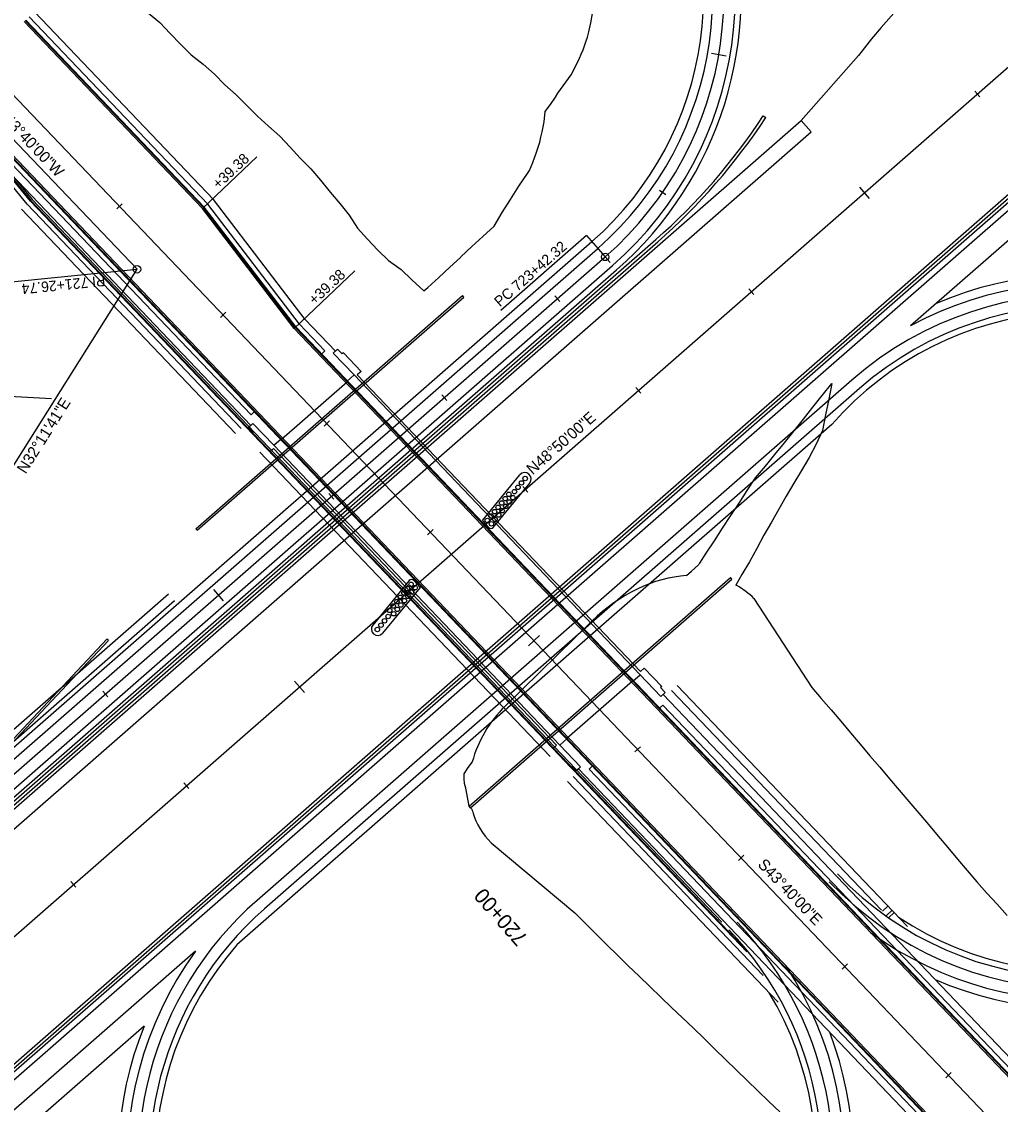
# Model space of a CAD drawing. Extents: x 1300404 to 1323571, y 237813 to 252077.
# Drawn here: x 1310501 to 1311153, y 240634 to 241355 of the extents above; entities that cross this region are included whole.
import ezdxf

# ---------------------------------------------------------------- set-up
doc = ezdxf.new("R2010")
doc.units = 0
for name, color, linetype in [('R_Attenuator', 7, 'Continuous'), ('R_Barrier Wall', 7, 'Continuous'), ('R_Bridge', 7, 'Continuous'), ('R_Bridge Wall', 7, 'Continuous'), ('R_Const Limits', 7, 'Continuous'), ('R_Curb', 7, 'Continuous'), ('R_Future', 7, 'Continuous'), ('R_Horz Alg Annot', 7, 'Continuous'), ('R_Horz Alg Annot Leader', 7, 'Continuous'), ('R_Horz Alg Major Ticks', 7, 'Continuous'), ('R_Horz Alg Minor Ticks', 7, 'Continuous'), ('R_Horz Alg Station Annot', 7, 'Continuous'), ('R_Horz Alg Tangents', 7, 'Continuous'), ('R_Horz Alg Tangents Text', 7, 'Continuous'), ('R_Lane Edge', 7, 'Continuous'), ('R_Proposed', 7, 'Continuous'), ('R_Shoulder', 7, 'Continuous'), ('R_Sidewalk Edge', 7, 'Continuous')]:
    doc.layers.add(name, color=color, linetype=linetype)

msp = doc.modelspace()

# ---------------------------------------------------------------- linework, layer by layer
at = {"layer": 'R_Attenuator'}
for p, q in [((1310807.94, 241022.48), (1310832.88, 241052.88)), ((1310815.12, 241017.82), (1310839.41, 241047.43)), ((1310812.06, 241017.77), (1310807.94, 241022.48)), ((1310759.18, 240982.48), (1310734.86, 240952.84)), ((1310762.21, 240982.5), (1310766.33, 240977.79)), ((1310766.33, 240977.79), (1310741.39, 240947.4))]:
    msp.add_line(p, q, dxfattribs=at)
for centre in [(1310831.59, 241044.6), (1310833.97, 241047.5), (1310836.35, 241050.4), (1310825.48, 241039.91), (1310828.19, 241037.69), (1310829.21, 241041.7), (1310818.34, 241031.21), (1310820.72, 241034.11), (1310823.1, 241037.01), (1310823.43, 241031.89), (1310825.81, 241034.79), (1310813.59, 241025.42), (1310815.97, 241028.31), (1310816.29, 241023.2), (1310818.67, 241026.09), (1310821.05, 241028.99), (1310811.21, 241022.52), (1310813.91, 241020.3), (1310760.36, 240979.97), (1310755.6, 240974.18), (1310757.98, 240977.08), (1310760.68, 240974.86), (1310763.06, 240977.75), (1310748.46, 240965.48), (1310750.84, 240968.38), (1310753.22, 240971.28), (1310753.55, 240966.16), (1310755.93, 240969.06), (1310758.3, 240971.96), (1310745.06, 240958.57), (1310746.08, 240962.58), (1310748.79, 240960.36), (1310751.17, 240963.26), (1310740.3, 240952.77), (1310742.68, 240955.67), (1310737.92, 240949.87)]:
    msp.add_circle(centre, 1.5, dxfattribs=at)
for centre, radius, start, end in [((1310836.13, 241050.13), 4.25, 320.63015, 139.81639), ((1310813.57, 241019.09), 2, 221.17359, 320.63075), ((1310760.7, 240981.18), 2, 41.17359, 140.63075), ((1310738.14, 240950.14), 4.25, 140.63015, 319.81639)]:
    msp.add_arc(centre, radius, start, end, dxfattribs=at)
at = {"layer": 'R_Barrier Wall'}
for p, q in [((1310994.97, 241291.94), (1310996.64, 241290.84)), ((1309593.62, 240046.84), (1310923.44, 241209.65)), ((1309594.94, 240045.34), (1310924.76, 241208.15)), ((1310489.06, 240870.1), (1310557.69, 240943.38)), ((1310490.03, 240869.19), (1310558.66, 240942.47)), ((1310558.66, 240942.47), (1310557.69, 240943.38))]:
    msp.add_line(p, q, dxfattribs=at)
for radius in [404.98, 406.98]:
    msp.add_arc((1310656.34, 241514.05), radius, 311.26571, 326.73874, dxfattribs=at)
at = {"layer": 'R_Bridge'}
for p, q in [((1310708.55, 241133.88), (1310711.44, 241136.64)), ((1310722.36, 241119.42), (1310708.55, 241133.88)), ((1310714.54, 241133.4), (1310711.44, 241136.64)), ((1310715.26, 241134.09), (1310714.54, 241133.4)), ((1310727.01, 241121.78), (1310715.26, 241134.09)), ((1310717.46, 241115.13), (1310722.36, 241119.42)), ((1310727, 241121.8), (1310724.52, 241119.44)), ((1310724.52, 241119.44), (1310913.14, 240921.84)), ((1310674.09, 241076.57), (1310717.79, 241114.79)), ((1310717.79, 241114.79), (1310717.46, 241115.13)), ((1310655.03, 241087.12), (1310652.14, 241084.35)), ((1310655.25, 241081.1), (1310652.14, 241084.35)), ((1310668.84, 241072.65), (1310655.03, 241087.12)), ((1310655.25, 241081.1), (1310654.52, 241080.41)), ((1310666.26, 241068.11), (1310654.52, 241080.41)), ((1310668.87, 241072.67), (1310673.74, 241076.93)), ((1310674.09, 241076.57), (1310673.74, 241076.93)), ((1310668.73, 241070.47), (1310666.26, 241068.11)), ((1310668.73, 241070.47), (1310857.35, 240872.87)), ((1310668.87, 241072.67), (1310668.84, 241072.65)), ((1310915.61, 240924.2), (1310913.14, 240921.84)), ((1310915.59, 240924.21), (1310927.35, 240911.9)), ((1310908.12, 240915.39), (1310912.99, 240919.65)), ((1310912.99, 240919.65), (1310913.01, 240919.67)), ((1310913.01, 240919.67), (1310926.82, 240905.21)), ((1310864.08, 240877.52), (1310907.78, 240915.74)), ((1310907.78, 240915.74), (1310908.12, 240915.39)), ((1310927.35, 240911.9), (1310926.62, 240911.21)), ((1310926.62, 240911.21), (1310929.71, 240907.97)), ((1310926.82, 240905.21), (1310929.71, 240907.97)), ((1310854.87, 240870.51), (1310857.35, 240872.87)), ((1310859.51, 240872.89), (1310864.41, 240877.18)), ((1310859.51, 240872.89), (1310873.32, 240858.43)), ((1310864.08, 240877.52), (1310864.41, 240877.18)), ((1310854.86, 240870.53), (1310866.61, 240858.21)), ((1310866.61, 240858.21), (1310867.34, 240858.9)), ((1310867.34, 240858.9), (1310870.43, 240855.66)), ((1310873.32, 240858.43), (1310870.43, 240855.66))]:
    msp.add_line(p, q, dxfattribs=at)
at = {"layer": 'R_Bridge Wall'}
for p, q in [((1310617, 241016.96), (1310794.66, 241172.31)), ((1310617.87, 241015.96), (1310795.53, 241171.31)), ((1310795.53, 241171.31), (1310794.66, 241172.31)), ((1310617.87, 241015.96), (1310617, 241016.96)), ((1310799.12, 240832.17), (1310973.27, 240984.44)), ((1310800, 240831.16), (1310974.14, 240983.43)), ((1310974.14, 240983.43), (1310973.27, 240984.44)), ((1310800, 240831.16), (1310799.12, 240832.17))]:
    msp.add_line(p, q, dxfattribs=at)
at = {"layer": 'R_Const Limits'}
for p, q in [((1310988.78, 240970.54), (1311027.32, 240911.3)), ((1310823.12, 240898.9), (1310880.92, 240955.54)), ((1310799.12, 240832.17), (1310800.89, 240830.14)), ((1310813.77, 240807.78), (1310869.51, 240761.06))]:
    msp.add_line(p, q, dxfattribs=at)
for points in [[(1311185.37, 241483.83), (1311167.13, 241464.86), (1311167.15, 241464.85), (1311162.87, 241459.25), (1311156.66, 241451.34), (1311153.67, 241440.35), (1311146.91, 241432.97), (1311139.94, 241425.8), (1311132.94, 241418.66), (1311125.71, 241411.74), (1311119.16, 241404.16), (1311112.06, 241397.12), (1311106.62, 241388.47), (1311100.11, 241380.86), (1311093.57, 241373.27), (1311086.77, 241365.95), (1311080.19, 241358.4), (1311073.62, 241350.85), (1311067.08, 241343.26), (1311060.89, 241335.34), (1311058.51, 241332.25), (1311020.24, 241288.97), (1311020.24, 241288.97)], [(1310585.25, 241360.65), (1310592.98, 241354.21), (1310599.76, 241346.86), (1310606.77, 241339.72), (1310613.83, 241332.64), (1310621.86, 241326.48), (1310629.31, 241319.77), (1310636.38, 241312.69), (1310643.86, 241306), (1310650.82, 241298.83), (1310657.93, 241291.79), (1310665.37, 241285.06), (1310672.88, 241278.41), (1310679.73, 241271.12), (1310686.52, 241263.78), (1310693.62, 241256.74), (1310700.09, 241249.08), (1310706.37, 241241.25), (1310712.81, 241233.58), (1310719.08, 241225.74), (1310724.68, 241217.25), (1310731.35, 241209.8), (1310738.15, 241202.47), (1310745.41, 241195.57), (1310753.67, 241189.63), (1310760.91, 241182.72), (1310768.85, 241175.36)], [(1310839.27, 241255.69), (1310839.27, 241255.69), (1310841.49, 241260.84), (1310843.87, 241267.73), (1310846.06, 241274.43), (1310846.91, 241277.88), (1310847.7, 241281.28), (1310849.05, 241288), (1310849.61, 241294.95), (1310853.25, 241299.62), (1310856.55, 241304.55), (1310858.13, 241307.06), (1310859.91, 241309.48), (1310863.56, 241314.35), (1310867.11, 241319.38), (1310869.81, 241324.85), (1310872.55, 241330.36), (1310873.77, 241333.2), (1310874.93, 241336.06), (1310877.05, 241341.89), (1310877.89, 241344.5), (1310878.8, 241347.86), (1310880.17, 241353.93), (1310881.19, 241360.09)], [(1310768.85, 241175.37), (1310771.5, 241177.75), (1310778.93, 241184.44), (1310786.26, 241191.26), (1310793.21, 241197.72), (1310793.58, 241198.08), (1310800.87, 241204.93), (1310808.19, 241211.75), (1310815.61, 241218.45), (1310820.95, 241227.54), (1310826.51, 241236.38), (1310832.2, 241245.06), (1310837.94, 241253.69), (1310839.27, 241255.69), (1310839.27, 241255.69)], [(1310943.96, 240985.79), (1310947.24, 240988.69), (1310951.89, 240992.93), (1310952.15, 240993.31), (1310952.55, 240993.92), (1310952.65, 240994.08), (1310956.95, 241000.61), (1310962.45, 241008.98), (1310967.82, 241017.42), (1310973.35, 241025.76), (1310978.89, 241034.1), (1310984.27, 241042.54), (1310989.93, 241050.81), (1310996.41, 241058.59), (1311002.8, 241066.42), (1311009.11, 241074.29), (1311015.49, 241082.13), (1311021.8, 241090.01), (1311028.05, 241097.93), (1311034.31, 241105.84), (1311040.66, 241113.69), (1311038.66, 241103.24), (1311036.53, 241092.87), (1311034.46, 241082.46), (1311030.27, 241073.32), (1311025.53, 241064.5), (1311020.53, 241055.84), (1311015.36, 241047.28), (1311010.37, 241038.61), (1311005.4, 241029.93), (1311000.43, 241021.25), (1310995.33, 241012.65), (1310990.62, 241003.82), (1310985.89, 240995), (1310980.66, 240986.47), (1310976.81, 240979.35)], [(1311027.33, 240911.29), (1311033.68, 240903.93), (1311040.19, 240896.32), (1311046.68, 240888.7), (1311053.17, 240881.07), (1311059.64, 240873.42), (1311066.1, 240865.76), (1311072.56, 240858.1), (1311079.08, 240850.5), (1311085.58, 240842.88), (1311092.07, 240835.25), (1311098.55, 240827.61), (1311105.01, 240819.96), (1311111.46, 240812.29), (1311117.9, 240804.61), (1311124.32, 240796.91), (1311130.76, 240789.24), (1311137.39, 240781.74), (1311144.05, 240774.27), (1311150.76, 240766.85), (1311157.47, 240759.43)], [(1310799.12, 240832.17), (1310796.95, 240844.17), (1310795.93, 240847.21), (1310795.63, 240850.43), (1310795.75, 240853.8), (1310798.3, 240857.98), (1310801.17, 240861.66)], [(1311005.93, 240628.61), (1310998.7, 240635.54), (1310991.49, 240642.48), (1310984.28, 240649.42), (1310977.09, 240656.38), (1310969.93, 240663.37), (1310962.78, 240670.37), (1310955.65, 240677.39), (1310948.44, 240684.33), (1310941.18, 240691.23), (1310933.93, 240698.14), (1310926.7, 240705.05), (1310919.48, 240711.99), (1310912.27, 240718.93), (1310905.07, 240725.89), (1310897.89, 240732.85), (1310890.72, 240739.83), (1310883.57, 240746.83), (1310876.53, 240753.94), (1310869.51, 240761.06), (1310869.51, 240761.06), (1310869.51, 240761.06), (1310869.51, 240761.06), (1310869.51, 240761.06), (1310869.51, 240761.06), (1310869.51, 240761.06), (1310869.51, 240761.06), (1310869.51, 240761.06)]]:
    msp.add_lwpolyline(points, dxfattribs=at)
for centre, major_axis, ratio, start_param, end_param in [((1310926.5, 240908.22), (-62.28, -62.32), 0.745616, 3.84485, 4.698226), ((1310926.5, 240908.22), (-62.28, -62.32), 0.745616, 3.358393, 3.367118), ((1310926.5, 240908.22), (-62.28, -62.32), 0.745616, 3.141593, 3.358393), ((1310862.67, 240857.7), (48.9, 49.92), 0.817242, 1.545592, 2.183789), ((1310862.67, 240857.7), (48.9, 49.92), 0.817242, 2.691395, 2.723332), ((1310862.67, 240857.7), (48.9, 49.92), 0.817242, 2.723644, 3.141593)]:
    msp.add_ellipse(centre, major_axis=major_axis, ratio=ratio, start_param=start_param, end_param=end_param, dxfattribs=at)
at = {"layer": 'R_Curb'}
for p, q in [((1310503.29, 241355.44), (1310622.23, 241230.84)), ((1310503.65, 241355.78), (1310622.61, 241231.16)), ((1310431.61, 241329.88), (1310671.61, 241078.44)), ((1310431.97, 241330.23), (1310671.99, 241078.77)), ((1310683.32, 241150.91), (1310622.23, 241230.84)), ((1310683.7, 241151.23), (1310622.61, 241231.16)), ((1310683.32, 241150.91), (1311065.94, 240750.04)), ((1310683.7, 241151.23), (1311067.92, 240748.69)), ((1310671.61, 241078.44), (1311009.39, 240724.57)), ((1310671.99, 241078.77), (1311008.13, 240726.61)), ((1311065.94, 240750.04), (1311239.97, 240567.73)), ((1311067.92, 240748.69), (1311240.13, 240568.28)), ((1311008.13, 240726.61), (1311199.03, 240526.61)), ((1311009.39, 240724.57), (1311198.47, 240526.48))]:
    msp.add_line(p, q, dxfattribs=at)
at = {"layer": 'R_Future'}
for p, q in [((1311714.76, 241726.24), (1309950.43, 240183.5)), ((1311716.07, 241724.73), (1309951.75, 240181.99)), ((1311717.39, 241723.23), (1309953.06, 240180.49)), ((1311720.02, 241720.22), (1309955.69, 240177.48)), ((1311729.9, 241708.92), (1311093.16, 241152.15)), ((1310504.53, 241233.21), (1310408.91, 241349.31)), ((1310506.77, 241235.21), (1310411.16, 241351.31)), ((1310411.52, 241351.65), (1310507.13, 241235.55)), ((1310412.25, 241352.34), (1310507.86, 241236.24)), ((1310506.77, 241235.21), (1310984.1, 240735.13)), ((1310506.77, 241235.21), (1310984.1, 240735.13)), ((1310507.13, 241235.55), (1310981.19, 240738.9)), ((1310507.13, 241235.55), (1310981.19, 240738.9)), ((1310507.86, 241236.24), (1310967.32, 240754.88)), ((1310507.86, 241236.24), (1310967.32, 240754.88)), ((1310500.78, 241229.89), (1310643.48, 241080.39)), ((1310504.53, 241233.21), (1310647.25, 241083.69)), ((1311054.08, 241115.99), (1310657.74, 240769.43)), ((1310426.48, 241108.99), (1310520.85, 241103.66)), ((1311059.02, 241110.35), (1310662.67, 240763.78)), ((1311040.69, 241086.35), (1310644.34, 240739.78)), ((1310659.55, 241067.9), (1310853.07, 240865.17)), ((1309569.9, 240073.92), (1310598.82, 240973.62)), ((1309573.85, 240069.41), (1310602.77, 240969.1)), ((1310933.94, 240909.34), (1311073.7, 240762.92)), ((1310937.71, 240912.63), (1311091.03, 240752)), ((1310868.38, 240852.02), (1310994.91, 240719.46)), ((1310864.62, 240848.72), (1311005.01, 240701.64)), ((1311074.39, 240762.19), (1311078.01, 240765.65)), ((1311077.15, 240759.3), (1311080.77, 240762.75)), ((1311078.53, 240757.85), (1311082.15, 240761.3)), ((1310616.69, 240735.53), (1309965.57, 240166.18)), ((1310582.45, 240685.67), (1309975.44, 240154.89))]:
    msp.add_line(p, q, dxfattribs=at)
for centre, radius, start, end in [((1311206.47, 240941.72), 245, 246.68093, 113.15991), ((1311206.47, 240941.72), 239, 234.16397, 118.30111), ((1311206.47, 240941.72), 231.5, 223.66667, 131.16667), ((1311206.47, 240941.72), 231.5, 223.66667, 131.16667), ((1311206.47, 240941.72), 220, 236.50529, 138.89832), ((1311206.47, 240941.72), 224, 223.66667, 131.16667), ((1310810.12, 240595.16), 231.5, 131.16667, 43.66667), ((1310810.12, 240595.16), 231.5, 131.16667, 43.66667), ((1310810.12, 240595.16), 224, 131.16667, 43.66667), ((1310810.12, 240595.16), 220, 138.89832, 30.82805), ((1310810.12, 240595.16), 239, 144.03223, 33.16936), ((1310810.12, 240595.16), 245, 158.31916, 20.65241)]:
    msp.add_arc(centre, radius, start, end, dxfattribs=at)
at = {"layer": 'R_Horz Alg Annot Leader'}
for p, q in [((1310621.46, 241230.19), (1310657.67, 241264.74)), ((1310682.55, 241150.26), (1310722.85, 241188.72))]:
    msp.add_line(p, q, dxfattribs=at)
for points in [[(1310877.14, 241212.38), (1310820.15, 241162.42)], [(1310877.14, 241212.38), (1310889.67, 241198.05)], [(1310494.1, 241181.4), (1310577.76, 241189.8)]]:
    msp.add_lwpolyline(points, dxfattribs=at)
at = {"layer": 'R_Horz Alg Major Ticks'}
for points in [[(1310960.47, 241333.74), (1310970.33, 241332.04)], [(1311059.07, 241244.56), (1311065.66, 241237.03)], [(1310886.38, 241201.81), (1310892.96, 241194.29)], [(1310886.38, 241201.81), (1310892.96, 241194.29)], [(1310886.38, 241201.81), (1310892.96, 241194.29)], [(1310628.68, 240976.48), (1310635.27, 240968.95)], [(1310845.86, 240945.85), (1310838.63, 240938.95)], [(1310682.68, 240915.43), (1310689.26, 240907.9)]]:
    msp.add_lwpolyline(points, dxfattribs=at)
at = {"layer": 'R_Horz Alg Minor Ticks'}
for points in [[(1311136, 241308.5), (1311139.29, 241304.74)], [(1310925.88, 241242.42), (1310930, 241239.59)], [(1310567.87, 241233.47), (1310564.25, 241230.02)], [(1310985.44, 241176.85), (1310988.73, 241173.09)], [(1310856.17, 241172.08), (1310859.46, 241168.31)], [(1310636.92, 241161.14), (1310633.3, 241157.68)], [(1310910.16, 241111.02), (1310913.45, 241107.26)], [(1310780.89, 241106.25), (1310784.18, 241102.49)], [(1310705.96, 241088.8), (1310702.35, 241085.35)], [(1310705.61, 241040.43), (1310708.9, 241036.66)], [(1310834.88, 241045.2), (1310838.17, 241041.44)], [(1310775.01, 241016.46), (1310771.39, 241013.01)], [(1310759.6, 240979.37), (1310762.89, 240975.61)], [(1310555.05, 240908.78), (1310558.34, 240905.01)], [(1310913.1, 240871.79), (1310909.48, 240868.34)], [(1310609.04, 240847.72), (1310612.33, 240843.96)], [(1310982.15, 240799.45), (1310978.53, 240796)], [(1310533.76, 240781.9), (1310537.05, 240778.14)], [(1311051.19, 240727.11), (1311047.58, 240723.66)], [(1311120.24, 240654.78), (1311116.62, 240651.33)]]:
    msp.add_lwpolyline(points, dxfattribs=at)
at = {"layer": 'R_Horz Alg Tangents'}
for p, q in [((1310577.76, 241189.8), (1310345.07, 241433.58)), ((1310398.2, 240904.62), (1310577.76, 241189.8))]:
    msp.add_line(p, q, dxfattribs=at)
at = {"layer": 'R_Lane Edge'}
for p, q in [((1310502.57, 241354.75), (1310621.46, 241230.19)), ((1310418.29, 241346.01), (1311200.16, 240526.88)), ((1311020.24, 241288.97), (1311026.82, 241281.45)), ((1309254.07, 239731.34), (1311026.82, 241281.45)), ((1310682.55, 241150.26), (1310621.46, 241230.19)), ((1310188.6, 240594.99), (1310884.73, 241203.69)), ((1309589.65, 240051.34), (1310894.61, 241192.4)), ((1310682.55, 241150.26), (1311239.63, 240566.63))]:
    msp.add_line(p, q, dxfattribs=at)
for radius in [239, 224]:
    msp.add_arc((1310737.29, 241372.32), radius, 311.16667, 114.47385, dxfattribs=at)
at = {"layer": 'R_Proposed'}
for p, q in [((1308427.57, 238936.91), (1312793.8, 242754.77)), ((1309180.37, 239595.16), (1312398.96, 242409.52)), ((1310151.78, 241665.77), (1311952.58, 239779.15)), ((1310165.59, 241651.3), (1311952.63, 239779.09)), ((1310165.59, 241651.3), (1311952.63, 239779.09)), ((1309584.71, 240056.98), (1310889.67, 241198.05))]:
    msp.add_line(p, q, dxfattribs=at)
for centre in [(1310889.67, 241198.05), (1310889.67, 241198.05), (1310577.76, 241189.8)]:
    msp.add_circle(centre, 2.5, dxfattribs=at)
msp.add_arc((1310737.29, 241372.32), 231.5, 311.16667, 114.47385, dxfattribs=at)
at = {"layer": 'R_Shoulder'}
for p, q in [((1309482.39, 239944.26), (1311020.24, 241288.97)), ((1310239.17, 240647.18), (1310880.78, 241208.21)), ((1309592.28, 240048.33), (1310897.24, 241189.39))]:
    msp.add_line(p, q, dxfattribs=at)
for radius, end in [(243, 77.31825), (218, 114.47385)]:
    msp.add_arc((1310737.29, 241372.32), radius, 311.16667, end, dxfattribs=at)
at = {"layer": 'R_Sidewalk Edge'}
for p, q in [((1310505.82, 241357.86), (1310624.89, 241233.11)), ((1310509.44, 241361.31), (1310628.7, 241236.36)), ((1310450.7, 241298.29), (1310653.59, 241085.74)), ((1310451.99, 241304.18), (1310653.75, 241092.8)), ((1310689.79, 241156.43), (1310628.7, 241236.36)), ((1310685.98, 241153.18), (1310624.89, 241233.11)), ((1310689.79, 241156.43), (1310710, 241135.26)), ((1310685.98, 241153.18), (1310702.93, 241135.43)), ((1310700.76, 241133.36), (1310702.93, 241135.43)), ((1310711.44, 241136.64), (1310710, 241135.26)), ((1310722.36, 241119.42), (1310913.01, 240919.67)), ((1310655.92, 241094.88), (1310653.75, 241092.8)), ((1310653.59, 241085.74), (1310652.14, 241084.35)), ((1310668.84, 241072.65), (1310859.51, 240872.89)), ((1310929.71, 240907.97), (1310928.27, 240906.59)), ((1310928.27, 240906.59), (1311249.89, 240569.63)), ((1310925.93, 240897.45), (1310928.1, 240899.52)), ((1310928.1, 240899.52), (1311244.64, 240567.9)), ((1310881.12, 240858.95), (1310878.95, 240856.88)), ((1310871.88, 240857.04), (1310870.43, 240855.66)), ((1310871.88, 240857.04), (1311196.44, 240517.02)), ((1310878.95, 240856.88), (1311198.54, 240522.06))]:
    msp.add_line(p, q, dxfattribs=at)

# ---------------------------------------------------------------- texts
at = {"layer": 'R_Horz Alg Annot'}
for s, rotation, p in [('+39.38', 43.07689, (1310632.06, 241242.88)), ('PC 723+42.32', 41.16667, (1310819.54, 241164.4)), ('PI 721+26.74', 185.73602, (1310556.26, 241185.69)), ('+39.38', 43.07689, (1310696.1, 241165.7))]:
    msp.add_text(s, height=7, rotation=rotation, dxfattribs=at).set_placement(p)
at = {"layer": 'R_Horz Alg Station Annot'}
msp.add_text('720+00', height=10, rotation=131.16667, dxfattribs=at).set_placement((1310838.66, 240744.64))
at = {"layer": 'R_Horz Alg Tangents Text'}
for s, rotation, p in [('N43%%d40\'00"W', 313.66667, (1310483.27, 241293.8)), ('N32%%d11\'41"E', 57.80537, (1310503.58, 241053.07)), ('N48%%d50\'00"E', 41.16667, (1310841.31, 241052.54)), ('S43%%d40\'00"E', 313.66667, (1310990.83, 240792.85))]:
    msp.add_text(s, height=7.5, rotation=rotation, dxfattribs=at).set_placement(p)

doc.saveas('drawing.dxf')
